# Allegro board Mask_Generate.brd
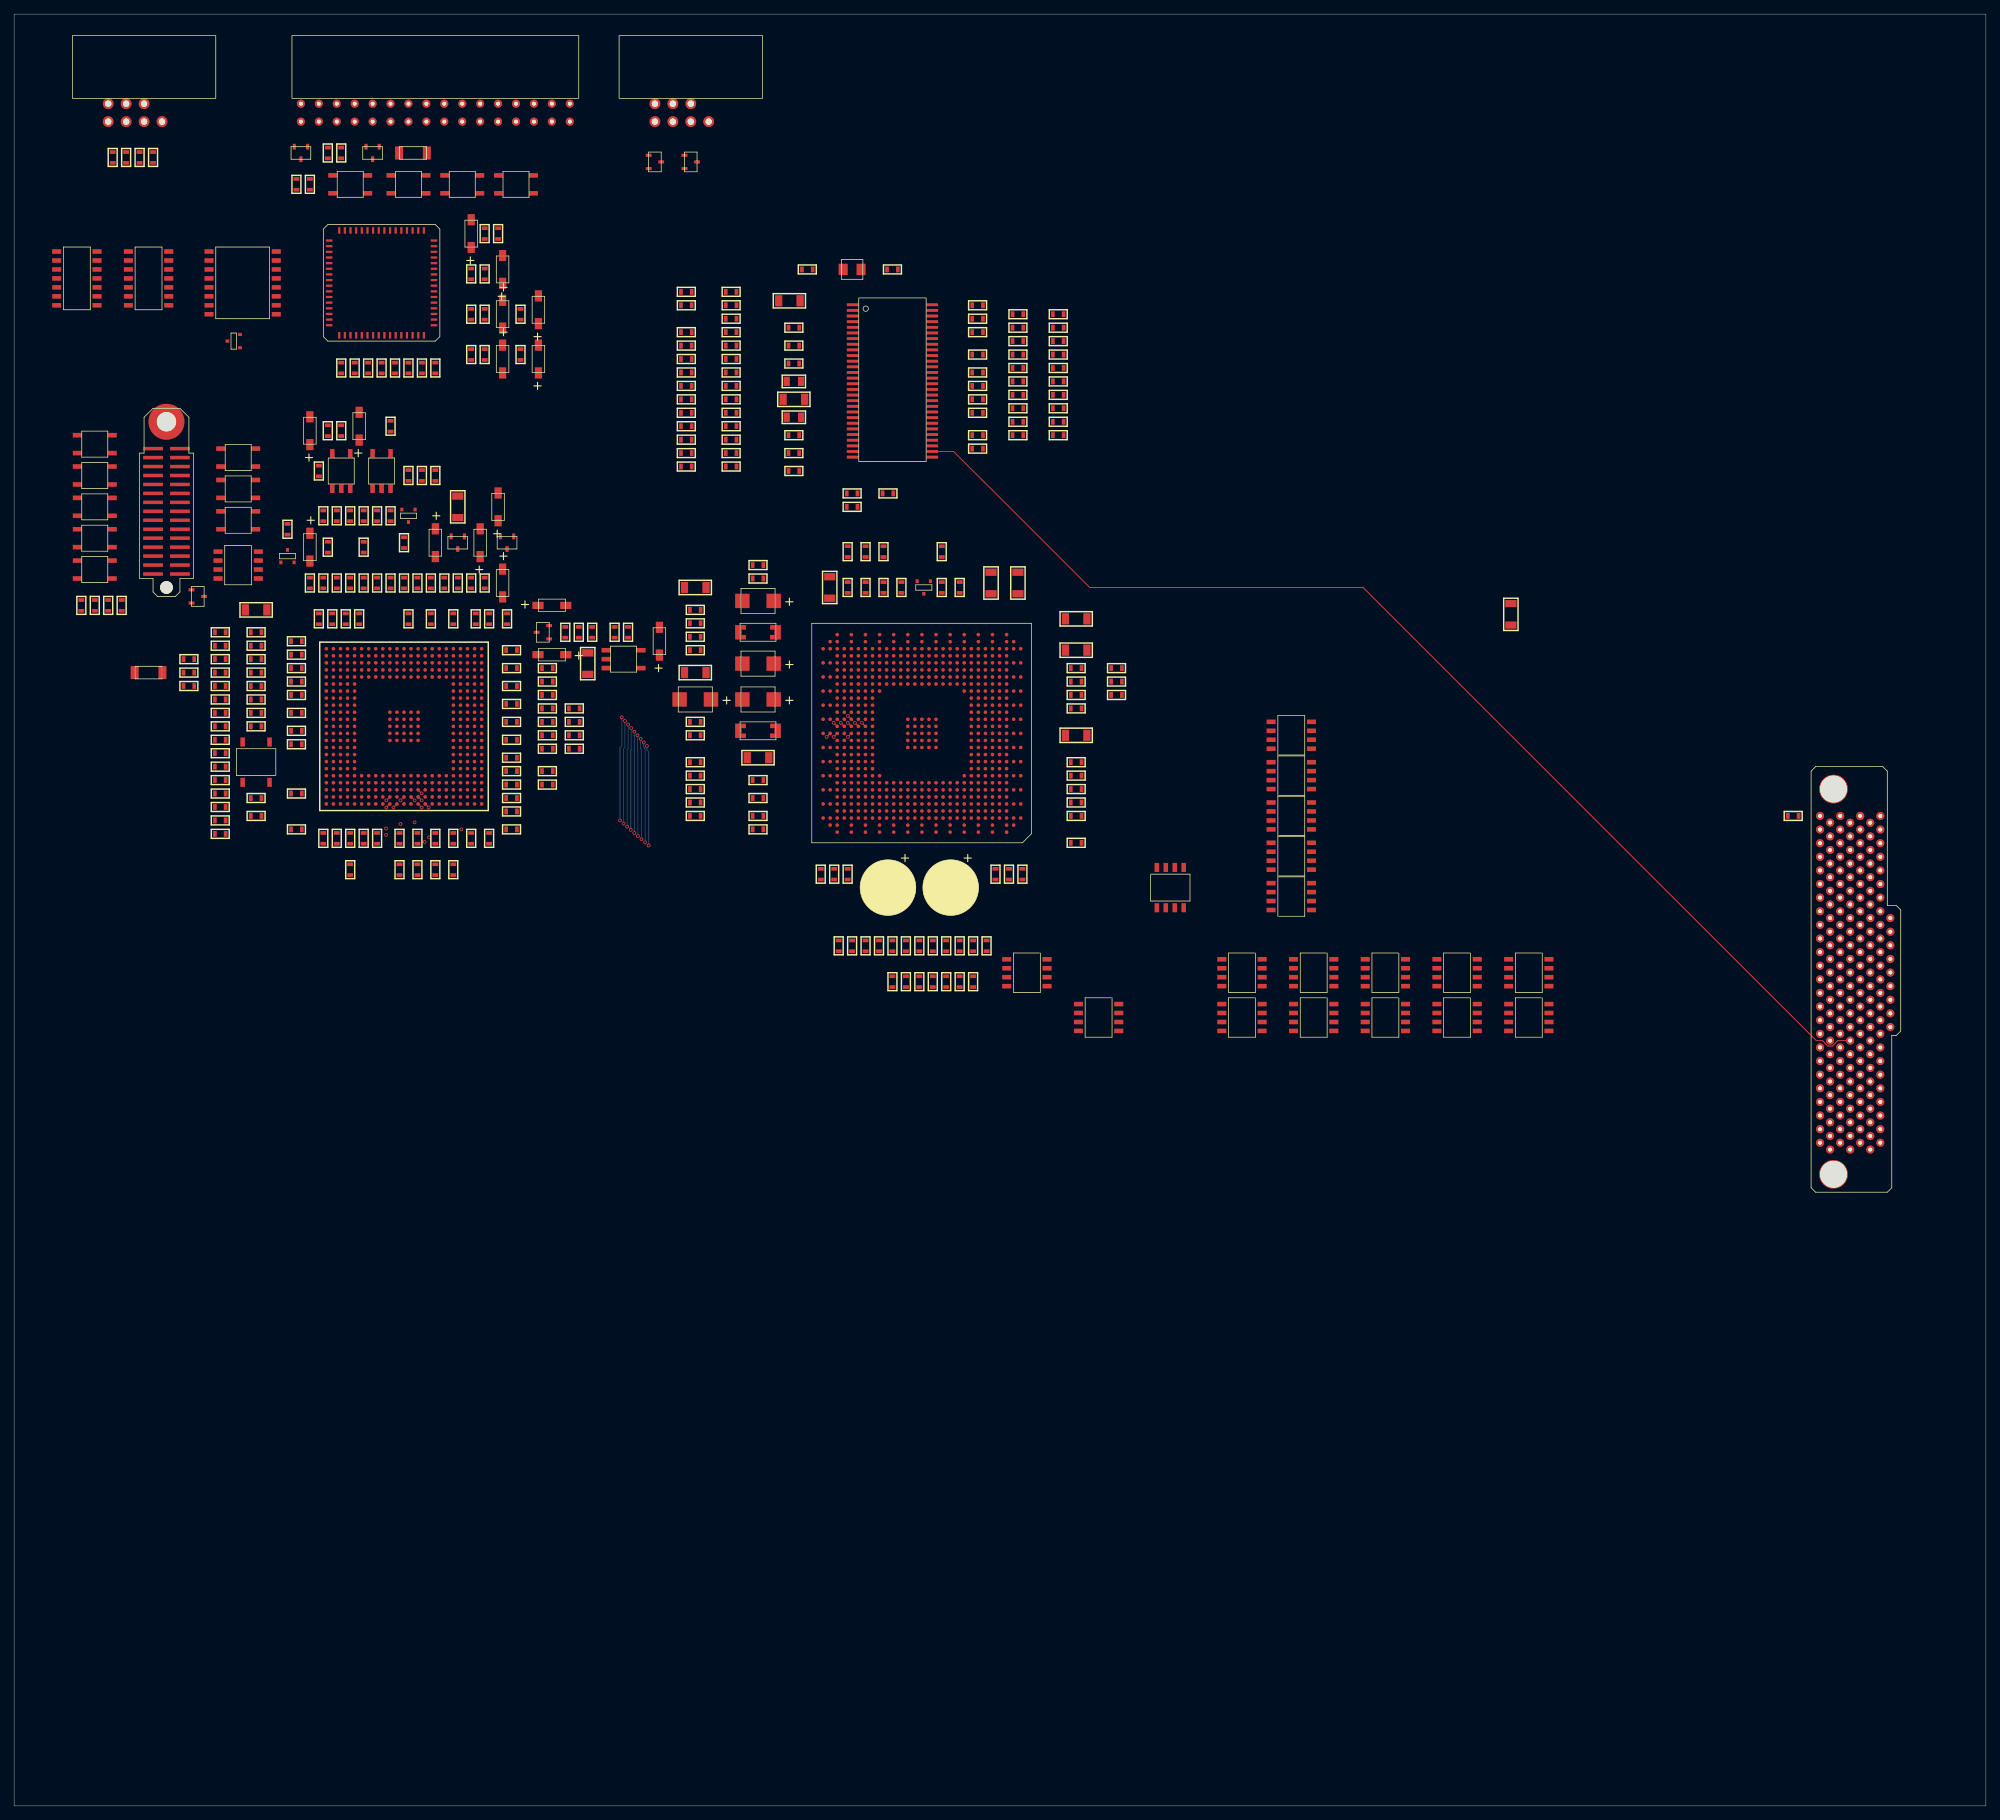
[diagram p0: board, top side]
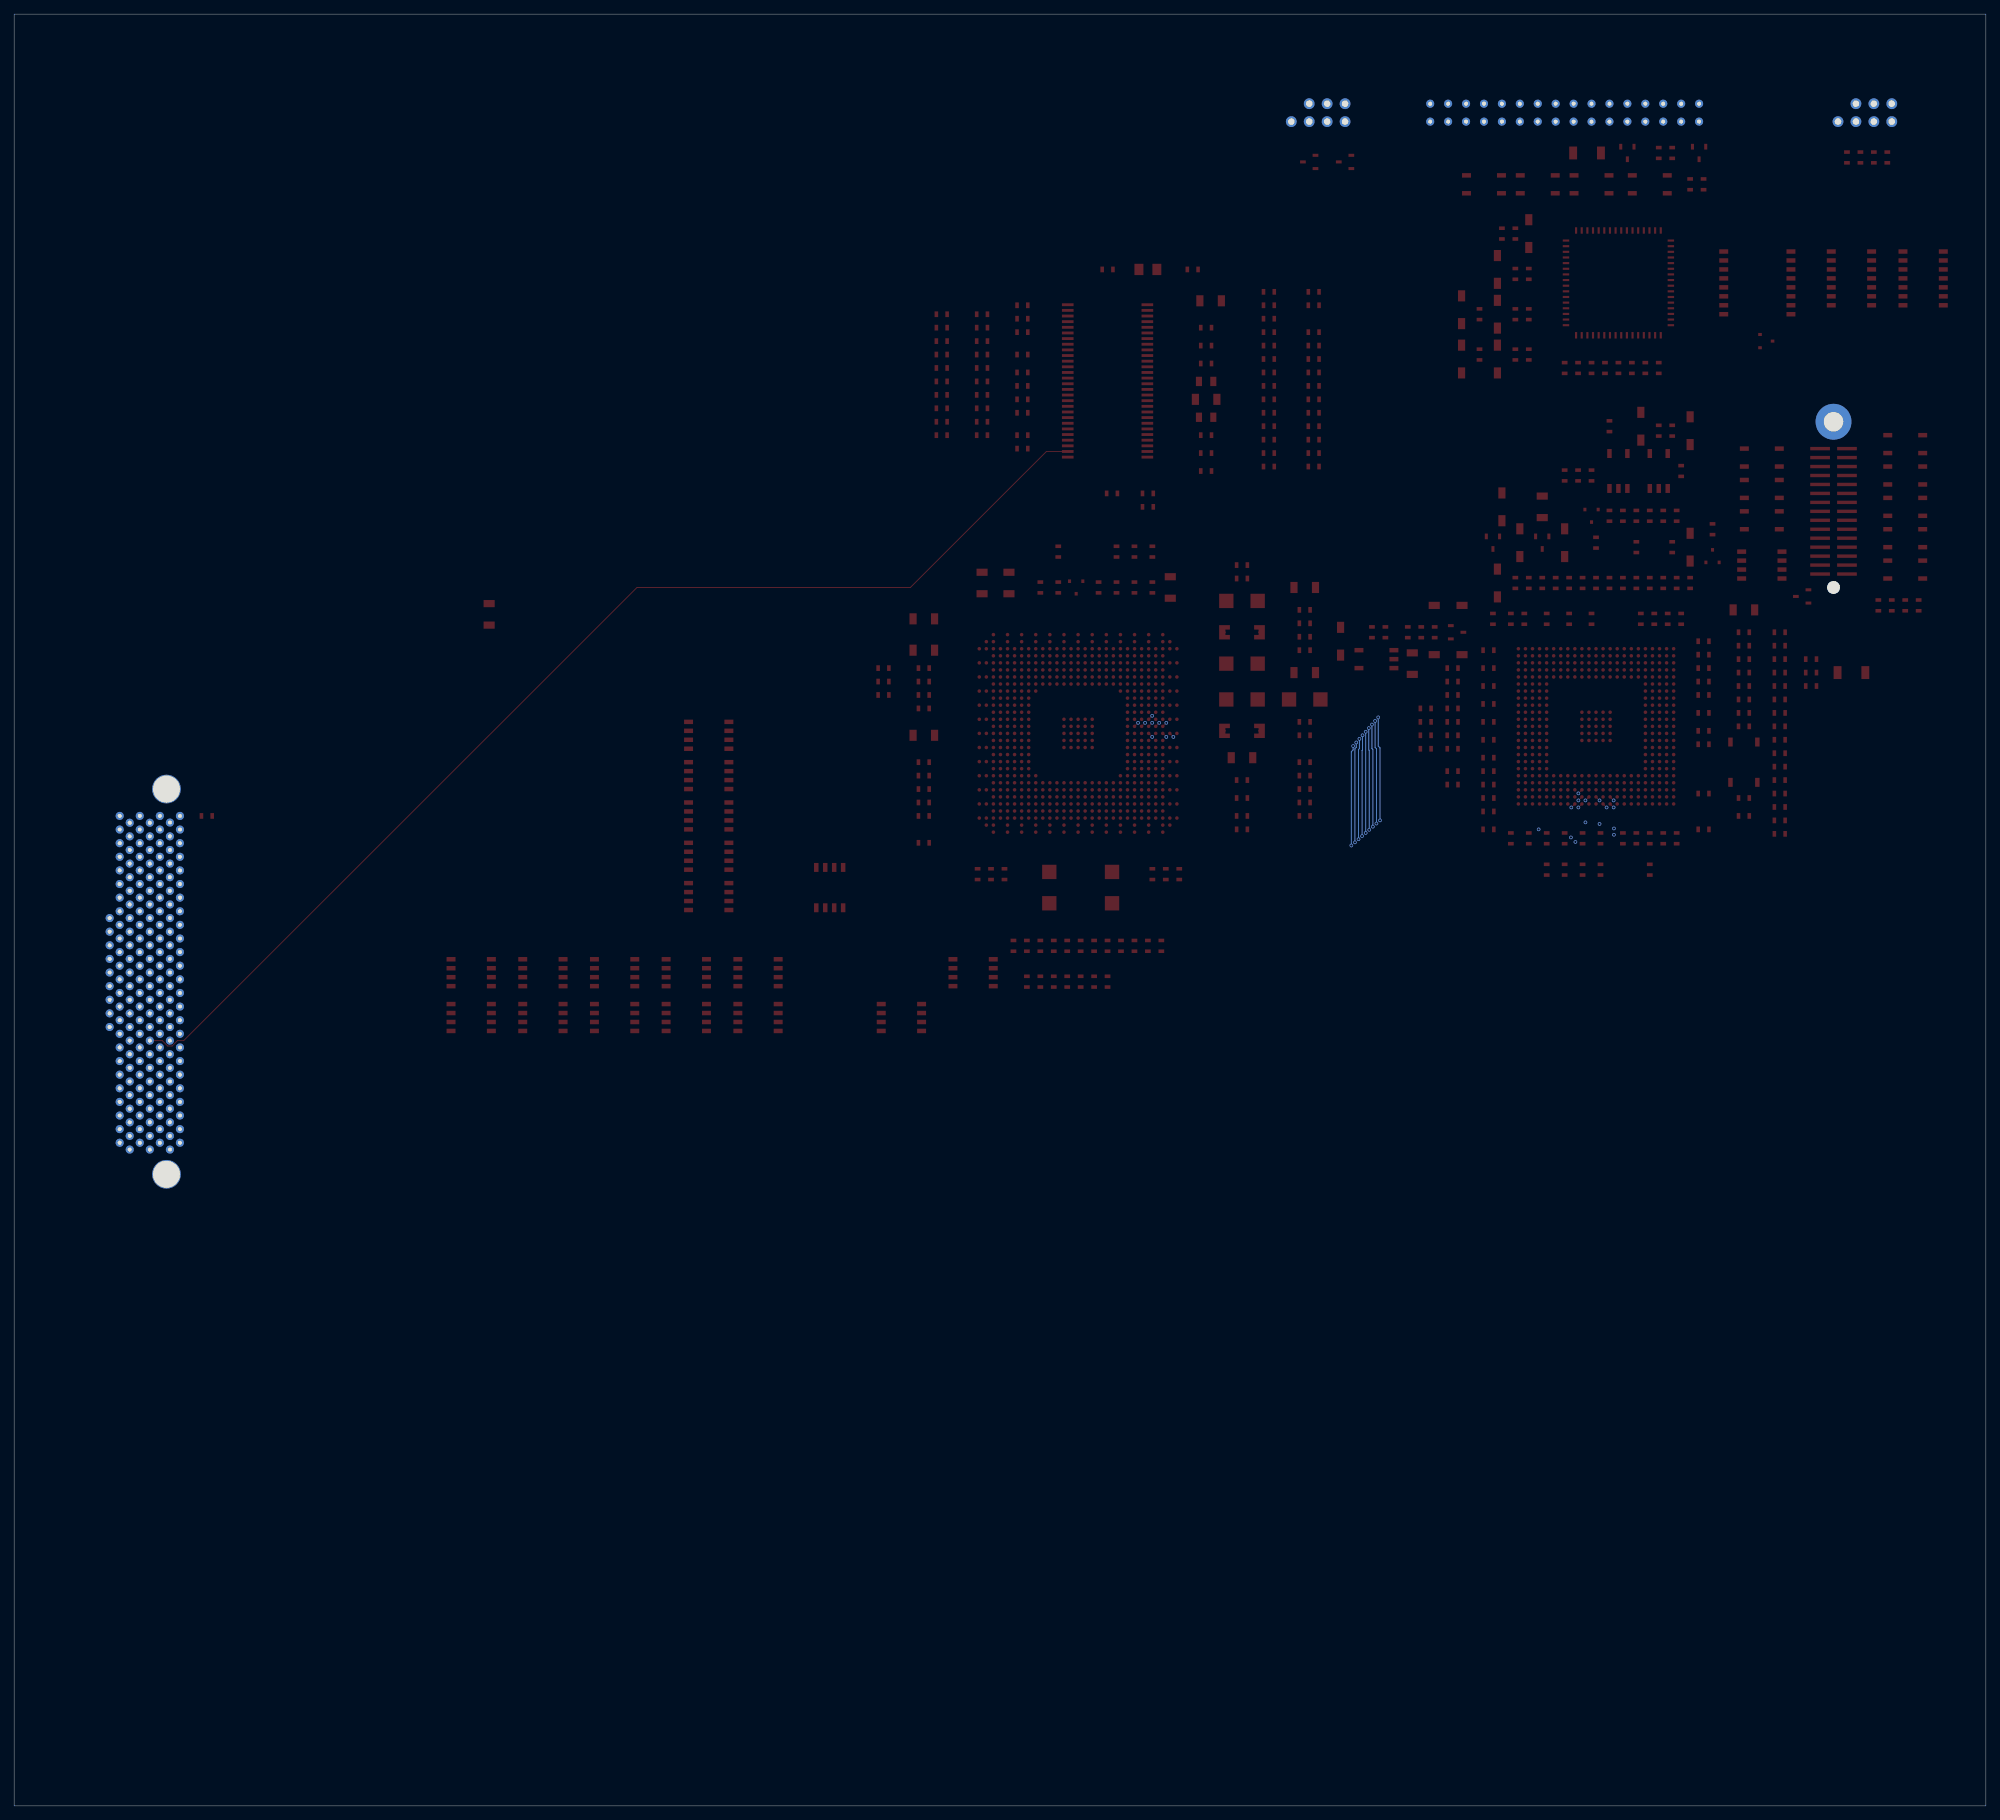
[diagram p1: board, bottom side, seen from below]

Outline 279.4 x 254 mm; copper layers: TOP, PLA2, INT3, INT4, PLA5, INT6, INT7, PLA8, INT9, INT10, PLA11, BOTTOM. Coordinates in mm from the lower left corner of the outline.
Outline path: 0,254 279.4,254 279.4,0 0,0 0,254

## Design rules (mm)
constraint set DEFAULT: min track width 0.127
net group ACTIVITY: nets ACT_1 ACTIVITY
net group AGP_REF: nets AGP_REF AGP_REFX
net group BSEL0: nets BSEL0 BSELX0
net group CK_14M: nets CK_14M CK_14MX
net group CK_27: nets CK_27 CK_PAL
net group CK_AGP66: nets CK_AGP66 CK_AGP66X
net group CK_CPLD: nets CK_CPLD CK_CPLDX
net group CK_CPU+: nets CK_CPU+ CK_CPUX+
net group CK_CPU-: nets CK_CPU- CK_CPUX-
net group CK_FWH: nets CK_FWH CK_FWHX
net group CK_ICH33: nets CK_ICH33 CK_ICH33X
net group CK_ICH48: nets CK_ICH48 CK_ICH48X
net group CK_ICH66: nets CK_ICH66 CK_ICH66X
net group CK_ITP+: nets CK_ITP+ CK_ITPX+
net group CK_ITP-: nets CK_ITP- CK_ITPX-
net group CK_LAN: nets CK_LAN CK_LANX
net group CK_LPC0: nets CK_LPC0 CK_LPC0X
net group CK_LPC1: nets CK_LPC1 CK_LPC1X
net group CK_MCH66: nets CK_MCH66 CK_MCH66X
net group CK_MCH+: nets CK_MCH+ CK_MCHX+
net group CK_MCH-: nets CK_MCH- CK_MCHX-
net group CK_MPCI: nets CK_MPCI CK_MPCIX
net group CK_RES0: nets CK_RES0 CK_RESX0
net group CK_RES1: nets CK_RES1 CK_RESX1
net group CK_RES2: nets CK_RES2 CK_RESX2
net group CK_SLOT1: nets CK_SLOT1 CK_SLOT1X
net group CK_SLOT2: nets CK_SLOT2 CK_SLOT2X
net group CK_SLOT3: nets CK_SLOT3 CK_SLOT3X
net group COMPFLT1: nets COMPFLT1 ITV_CVBS
net group DP1_CK_SCK+<0>: nets CK_SCK+<0> CK_SCK-<0>
net group DP1_CK_SCK+<5>: nets CK_SCK+<5> CK_SCK-<5>
net group DP_CK_SCK+<1>: nets CK_SCK+<1> CK_SCK-<1>
net group DP_CK_SCK+<2>: nets CK_SCK+<2> CK_SCK-<2>
net group DP_CK_SCK+<3>: nets CK_SCK+<3> CK_SCK-<3>
net group DP_CK_SCK+<4>: nets CK_SCK+<4> CK_SCK-<4>
net group DP_G_ADSTB0: nets G_ADSTB0+ G_ADSTB0-
net group DP_G_ADSTB1: nets G_ADSTB1+ G_ADSTB1-
net group DP_G_SBSTB: nets G_SBSTB+ G_SBSTB-
net group DP_H_DSTBN*<0>: nets H_DSTBN*<0> H_DSTBP*<0>
net group DP_H_DSTBN*<1>: nets H_DSTBN*<1> H_DSTBP*<1>
net group DP_H_DSTBN*<2>: nets H_DSTBN*<2> H_DSTBP*<2>
net group DP_H_DSTBN*<3>: nets H_DSTBN*<3> H_DSTBP*<3>
net group DP_H_HISTB: nets H_HISTB+ H_HISTB-
net group EXT_SWING: nets EXT_SWING V_AVCC1
net group G_AD<16>: nets G_AD<16> G_IDSEL
net group G_ST: nets G_ST<0> G_ST<2>
net group G_ST1X: nets G_ST1X G_ST<1>
net group H_ADSTB*: nets H_ADSTB*<0> H_ADSTB*<1>
net group M_D<0>: nets M_D<0> M_DX0
net group M_D<1>: nets M_D<1> M_DX1
net group M_D<2>: nets M_D<2> M_DX2
net group M_D<3>: nets M_D<3> M_DX3
net group M_D<4>: nets M_D<4> M_DX4
net group M_D<5>: nets M_D<5> M_DX5
net group M_D<6>: nets M_D<6> M_DX6
net group M_D<7>: nets M_D<7> M_DX7
net group M_D<8>: nets M_D<8> M_DX8
net group M_D<9>: nets M_D<9> M_DX9
net group M_D<10>: nets M_D<10> M_DX10
net group M_D<11>: nets M_D<11> M_DX11
net group M_D<12>: nets M_D<12> M_DX12
net group M_D<13>: nets M_D<13> M_DX13
net group M_D<14>: nets M_D<14> M_DX14
net group M_D<15>: nets M_D<15> M_DX15
net group M_D<16>: nets M_D<16> M_DX16
net group M_D<17>: nets M_D<17> M_DX17
net group M_D<18>: nets M_D<18> M_DX18
net group M_D<19>: nets M_D<19> M_DX19
net group M_D<20>: nets M_D<20> M_DX20
net group M_D<21>: nets M_D<21> M_DX21
net group M_D<22>: nets M_D<22> M_DX22
net group M_D<23>: nets M_D<23> M_DX23
net group M_D<24>: nets M_D<24> M_DX24
net group M_D<25>: nets M_D<25> M_DX25
net group M_D<26>: nets M_D<26> M_DX26
net group M_D<27>: nets M_D<27> M_DX27
net group M_D<28>: nets M_D<28> M_DX28
net group M_D<29>: nets M_D<29> M_DX29
net group M_D<30>: nets M_D<30> M_DX30
net group M_D<31>: nets M_D<31> M_DX31
net group M_D<32>: nets M_D<32> M_DX32
net group M_D<33>: nets M_D<33> M_DX33
net group M_D<34>: nets M_D<34> M_DX34
net group M_D<35>: nets M_D<35> M_DX35
net group M_D<36>: nets M_D<36> M_DX36
net group M_D<37>: nets M_D<37> M_DX37
net group M_D<38>: nets M_D<38> M_DX38
net group M_D<39>: nets M_D<39> M_DX39
net group M_D<40>: nets M_D<40> M_DX40
net group M_D<41>: nets M_D<41> M_DX41
net group M_D<42>: nets M_D<42> M_DX42
net group M_D<43>: nets M_D<43> M_DX43
net group M_D<44>: nets M_D<44> M_DX44
net group M_D<45>: nets M_D<45> M_DX45
net group M_D<46>: nets M_D<46> M_DX46
net group M_D<47>: nets M_D<47> M_DX47
net group M_D<48>: nets M_D<48> M_DX48
net group M_D<49>: nets M_D<49> M_DX49
net group M_D<50>: nets M_D<50> M_DX50
net group M_D<51>: nets M_D<51> M_DX51
net group M_D<52>: nets M_D<52> M_DX52
net group M_D<53>: nets M_D<53> M_DX53
net group M_D<54>: nets M_D<54> M_DX54
net group M_D<55>: nets M_D<55> M_DX55
net group M_D<56>: nets M_D<56> M_DX56
net group M_D<57>: nets M_D<57> M_DX57
net group M_D<58>: nets M_D<58> M_DX58
net group M_D<59>: nets M_D<59> M_DX59
net group M_D<60>: nets M_D<60> M_DX60
net group M_D<61>: nets M_D<61> M_DX61
net group M_D<62>: nets M_D<62> M_DX62
net group M_D<63>: nets M_D<63> M_DX63
net group M_SBS0: nets M_SBS0 M_SBSX0
net group M_SBS1: nets M_SBS1 M_SBSX1
net group M_SCAS*: nets M_SCAS* M_SCASX*
net group M_SCB<0>: nets M_SCB<0> M_SCBX0
net group M_SCB<1>: nets M_SCB<1> M_SCBX1
net group M_SCB<2>: nets M_SCB<2> M_SCBX2
net group M_SCB<3>: nets M_SCB<3> M_SCBX3
net group M_SCB<4>: nets M_SCB<4> M_SCBX4
net group M_SCB<5>: nets M_SCB<5> M_SCBX5
net group M_SCB<6>: nets M_SCB<6> M_SCBX6
net group M_SCB<7>: nets M_SCB<7> M_SCBX7
net group M_SDQS<0>: nets M_SDQS<0> M_SDQSX0
net group M_SDQS<1>: nets M_SDQS<1> M_SDQSX1
net group M_SDQS<2>: nets M_SDQS<2> M_SDQSX2
net group M_SDQS<3>: nets M_SDQS<3> M_SDQSX3
net group M_SDQS<4>: nets M_SDQS<4> M_SDQSX4
net group M_SDQS<5>: nets M_SDQS<5> M_SDQSX5
net group M_SDQS<6>: nets M_SDQS<6> M_SDQSX6
net group M_SDQS<7>: nets M_SDQS<7> M_SDQSX7
net group M_SDQS<8>: nets M_SDQS<8> M_SDQSX8
net group M_SMA<0>: nets M_SMA<0> M_SMAX0
net group M_SMA<1>: nets M_SMA<1> M_SMAX1
net group M_SMA<2>: nets M_SMA<2> M_SMAX2
net group M_SMA<3>: nets M_SMA<3> M_SMAX3
net group M_SMA<4>: nets M_SMA<4> M_SMAX4
net group M_SMA<5>: nets M_SMA<5> M_SMAX5
net group M_SMA<6>: nets M_SMA<6> M_SMAX6
net group M_SMA<7>: nets M_SMA<7> M_SMAX7
net group M_SMA<8>: nets M_SMA<8> M_SMAX8
net group M_SMA<9>: nets M_SMA<9> M_SMAX9
net group M_SMA<10>: nets M_SMA<10> M_SMAX10
net group M_SMA<11>: nets M_SMA<11> M_SMAX11
net group M_SMA<12>: nets M_SMA<12> M_SMAX12
net group M_SRAS*: nets M_SRAS* M_SRASX*
net group M_SWE*: nets M_SWE* M_SWEX*
net group MSEN: nets MSEN MSENX
net group MVREF: nets MVREF V_VDD2
net group TMDS0+: nets TMDS0+ TMDS0C+
net group TMDS0-: nets TMDS0- TMDS0C-
net group TMDS1+: nets TMDS1+ TMDS1C+
net group TMDS1-: nets TMDS1- TMDS1C-
net group TMDS2+: nets TMDS2+ TMDS2C+
net group TMDS2-: nets TMDS2- TMDS2C-
net group TMDSCLK+: nets TMDSCLK+ TMDSCLKC+
net group TMDSCLK-: nets TMDSCLK- TMDSCLKC-
net group TX0+: nets TX0+ TX0C+
net group TX0-: nets TX0- TX0C-
net group TX1+: nets TX1+ TX1C+
net group TX1-: nets TX1- TX1C-
net group TX2+: nets TX2+ TX2C+
net group TX2-: nets TX2- TX2C-
net group TX5+: nets TX5+ TX5C+
net group TX5-: nets TX5- TX5C-
net group TX6+: nets TX6+ TX6C+
net group TX6-: nets TX6- TX6C-
net group TXCLK1+: nets TXCLK1+ TXCLK1C+
net group TXCLK1-: nets TXCLK1- TXCLK1C-
net group TXCLK2+: nets TXCLK2+ TXCLK2C+
net group TXCLK2-: nets TXCLK2- TXCLK2C-
net group ACT_2: nets ACT_2 ADJ_VDD1 EN_LVD V_2V0_2V5
net group ADJ_LVD: nets ADJ_LVD ADJ_VDD2 V_2V5_LVD V_2V5_LVD1 V_2V5_LVD2 V_2V5_VDD
net group G_AD: nets G_AD<0> G_AD<1> G_AD<2> G_AD<3> G_AD<4> G_AD<5> G_AD<6> G_AD<7> G_AD<8> G_AD<9> G_AD<10> G_AD<11> G_AD<12> G_AD<13> G_AD<14> G_AD<15> G_AD<17> G_AD<18> G_AD<19> G_AD<20> G_AD<21> G_AD<22> G_AD<23> G_AD<24> G_AD<25> G_AD<26> G_AD<27> G_AD<28> G_AD<29> G_AD<30> G_AD<31>
net group G_C/BE*: nets G_C/BE*<0> G_C/BE*<1> G_C/BE*<2> G_C/BE*<3>
net group G_SBA: nets G_SBA<0> G_SBA<1> G_SBA<2> G_SBA<3> G_SBA<4> G_SBA<5> G_SBA<6> G_SBA<7>
net group H_A*: nets H_A*<3> H_A*<4> H_A*<5> H_A*<6> H_A*<7> H_A*<8> H_A*<9> H_A*<10> H_A*<11> H_A*<12> H_A*<13> H_A*<14> H_A*<15> H_A*<16> H_A*<17> H_A*<18> H_A*<19> H_A*<20> H_A*<21> H_A*<22> H_A*<23> H_A*<24> H_A*<25> H_A*<26> H_A*<27> H_A*<28> H_A*<29> H_A*<30> H_A*<31>
net group H_CPURST*: nets H_CPURST*
net group H_D: nets H_D<0> H_D<1> H_D<2> H_D<3> H_D<4> H_D<5> H_D<6> H_D<7> H_D<8> H_D<9> H_D<10> H_D<11> H_D<12> H_D<13> H_D<14> H_D<15> H_D<16> H_D<17> H_D<18> H_D<19> H_D<20> H_D<21> H_D<22> H_D<23> H_D<24> H_D<25> H_D<26> H_D<27> H_D<28> H_D<29> H_D<30> H_D<31> H_D<32> H_D<33> H_D<34> H_D<35> H_D<36> H_D<37> H_D<38> H_D<39> H_D<40> H_D<41> H_D<42> H_D<43> H_D<44> H_D<45> H_D<46> H_D<47> H_D<48> H_D<49> H_D<50> H_D<51> H_D<52> H_D<53> H_D<54> H_D<55> H_D<56> H_D<57> H_D<58> H_D<59> H_D<60> H_D<61> H_D<62> H_D<63>
net group H_DBI*: nets H_DBI*<0> H_DBI*<1> H_DBI*<2> H_DBI*<3>
net group H_HI: nets H_HI<0> H_HI<1> H_HI<2> H_HI<3> H_HI<4> H_HI<5> H_HI<6> H_HI<7> H_HI<8> H_HI<9> H_HI<10>
net group H_REQ*: nets H_REQ*<0> H_REQ*<1> H_REQ*<2> H_REQ*<3> H_REQ*<4>
net group H_RS*: nets H_RS*<0> H_RS*<1> H_RS*<2>
net group M_SCKE: nets M_SCKE<0> M_SCKE<1> M_SCKE<2> M_SCKE<3>
net group M_SCS*: nets M_SCS*<0> M_SCS*<1> M_SCS*<2> M_SCS*<3>
net group TX3+: nets TX3+ TX3_4+ TX3_4C+ TX4+
net group TX3-: nets TX3- TX3_4- TX3_4C- TX4-

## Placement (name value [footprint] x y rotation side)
C1  0.01PF  [C1206]  212.09 168.91 270 top
C61  0.1PF  [C0603]  96.52 153.67 180 top
C62  0.01PF  [C0603]  156.21 161.29 0 top
C63  0.01PF  [C0603]  96.52 151.76 180 top
C64  0.1PF  [C1206]  115.57 172.72 90 top
C65  0.1PF  [C1206]  138.43 173.35 90 top
C66  0.1PF  [C1206]  142.24 173.35 90 top
C67  0.1PF  [C0603]  150.49 147.95 0 top
C68  0.1PF  [C1206]  150.49 151.76 0 top
C69  10UF  [C1206]  150.49 163.83 0 top
C70  33UF  [TAJC]  105.41 156.84 180 top
C71  33UF  [TAJC]  105.41 161.92 180 top
C72  10UF  [C1206]  150.49 168.27 0 top
C73  0.1PF  [C0603]  96.52 147.95 180 top
C74  0.1PF  [C0603]  150.49 155.57 0 top
C75  100UF  [ELK01G]  132.72 130.17 270 top
C76  100UF  [TAJC]  96.52 156.84 180 top
C77  100UF  [ELK01G]  123.83 130.17 270 top
C78  100UF  [TAJC]  105.41 170.81 180 top
C79  0.1PF  [C0603]  118.11 132.08 270 top
C80  10UF  [C1206]  96.52 172.72 180 top
C81  10UF  [C1206]  105.41 148.59 180 top
C82  0.1PF  [C0603]  116.2 132.08 270 top
C83  10UF  [C1206]  96.52 160.66 180 top
C84  0.1PF  [C0603]  114.3 132.08 270 top
C85  0.1PF  [C0603]  142.88 132.08 270 top
C86  0.1PF  [C0603]  96.52 169.54 180 top
C87  0.1PF  [C0603]  105.41 140.34 180 top
C88  0.1PF  [C0603]  140.97 132.08 270 top
C89  0.1PF  [C0603]  105.41 175.89 180 top
C90  0.1PF  [C0603]  105.41 142.88 180 top
C91  0.1PF  [C0603]  139.06 132.08 270 top
C92  0.1PF  [C0603]  105.41 173.99 180 top
C93  0.1PF  [C0603]  105.41 145.41 180 top
C94  0.1PF  [C0603]  96.52 167.64 180 top
C95  0.1PF  [C0603]  96.52 165.73 180 top
C96  0.1PF  [C0603]  96.52 163.83 180 top
C97  10UF  [C1206]  109.86 213.36 180 top
C98  10UF  [C1206]  110.49 199.39 0 top
C99  0.1PF  [C0603]  110.49 194.31 180 top
C100  0.1PF  [C0603]  136.53 194.31 0 top
C101  0.1PF  [C0603]  110.49 191.77 180 top
C102  0.1PF  [C0603]  110.49 189.23 180 top
C103  0.01PF  [C0603]  110.49 209.55 180 top
C104  0.1PF  [C0603]  136.53 208.91 0 top
C105  0.01PF  [C0603]  110.49 204.47 180 top
C106  0.1PF  [C0603]  136.53 205.74 0 top
C107  0.01PF  [C0603]  110.49 207.01 180 top
C108  10PF  [C0603]  112.39 217.8 180 top
C109  10PF  [C0603]  124.46 217.8 0 top
C110  10PF  [C0603]  95.25 189.86 180 top
C111  10F  [C0603]  95.25 191.77 0 top
C112  10PF  [C0603]  95.25 193.67 0 top
C113  10PF  [C0603]  147.95 194.31 0 top
C114  10PF  [C0603]  147.95 196.21 0 top
C115  10PF  [C0603]  95.25 195.58 180 top
C116  10PF  [C0603]  147.95 198.12 180 top
C117  10PF  [C0603]  95.25 214.63 180 top
C118  10F  [C0603]  95.25 212.72 180 top
C119  10PF  [C0603]  95.25 208.91 0 top
C120  10PF  [C0603]  95.25 207.01 0 top
C121  10PF  [C0603]  95.25 205.1 0 top
C122  10PF  [C0603]  95.25 203.2 0 top
C123  10PF  [C0603]  95.25 201.29 0 top
C124  10PF  [C0603]  95.25 199.39 0 top
C125  10PF  [C0603]  95.25 197.48 180 top
C126  10PF  [C0603]  147.95 211.45 0 top
C127  0.1PF  [C0603]  252.09 140.34 180 top
C207  0.1PF  [C0603]  34.29 140.34 180 top
C208  0.1PF  [C0603]  64.77 205.74 270 top
C209  0.1PF  [C0603]  68.58 222.88 90 top
C210  0.1PF  [C0603]  64.77 211.45 270 top
C211  0.1PF  [C0603]  48.26 203.83 270 top
C212  0.1PF  [C0603]  66.67 205.74 270 top
C213  0.1PF  [C0603]  66.67 222.88 90 top
C214  0.1PF  [C0603]  66.67 211.45 270 top
C215  4UF  [TAJA]  69.22 205.1 270 top
C216  4UF  [TAJA]  64.77 222.88 90 top
C217  22UF  [TAJA]  69.22 211.45 270 top
C218  100PF  [C0603]  29.21 166.37 180 top
C219  22UF  [TAJA]  74.3 205.1 90 top
C220  22UF  [TAJA]  69.22 217.8 90 top
C221  22UF  [TAJA]  74.3 212.09 90 top
C222  47PF  [C0603]  29.21 160.66 180 top
C223  220PF  [C0603]  24.77 162.56 180 top
C224  0.1PF  [C0603]  44.45 234.31 270 top
C225  0.1PF  [C0603]  46.36 234.31 90 top
C226  22UF  [TAJA]  41.91 194.94 90 top
C227  22UF  [TAJA]  48.89 195.58 90 top
C228  22UF  [TAJA]  91.44 165.1 90 top
C229  0.1PF  [C0603]  46.36 194.94 90 top
C230  100PF  [C0603]  47.62 182.88 270 top
C231  100PF  [C0603]  51.44 182.88 270 top
C232  100PF  [C0603]  81.92 166.37 90 top
C233  4UF  [TAJA]  41.91 178.44 270 top
C234  22UF  [TAJA]  59.69 179.07 270 top
C235  0.1PF  [C0603]  55.25 179.07 270 top
C236  0.1PF  [C0603]  78.11 166.37 90 top
C237  22UF  [TAJA]  68.58 184.15 90 top
C238  22UF  [TAJA]  76.2 163.19 180 top
C239  4UF  [TAJA]  66.04 179.07 90 top
C240  4UF  [TAJA]  69.22 173.35 270 top
C241  4UF  [TAJA]  76.2 170.18 0 top
C242  0.1PF  [C0603]  75.56 144.78 0 top
C243  0.1PF  [C0603]  47.62 137.16 270 top
C244  0.1PF  [C0603]  40 163.19 180 top
C245  0.1PF  [C0603]  43.81 137.16 270 top
C246  0.1PF  [C0603]  70.48 142.88 0 top
C247  0.1PF  [C0603]  45.08 168.27 90 top
C248  0.1PF  [C0603]  70.48 138.43 0 top
C249  0.1PF  [C0603]  40 143.51 180 top
C250  0.1PF  [C0603]  67.31 137.16 270 top
C251  0.1PF  [C0603]  70.48 153.67 0 top
C252  0.1PF  [C0603]  46.99 168.27 90 top
C253  0.1PF  [C0603]  70.48 148.59 0 top
C254  0.1PF  [C0603]  62.23 168.27 90 top
C255  0.1PF  [C0603]  70.48 151.13 0 top
C256  0.1PF  [C0603]  57.15 137.16 270 top
C257  0.1PF  [C0603]  34.29 160.66 180 top
C258  0.1PF  [C0603]  34.29 154.94 180 top
C259  0.1PF  [C0603]  34.29 164.46 0 top
C260  0.1PF  [C0603]  29.21 147.32 180 top
C261  0.1PF  [C0603]  29.21 137.79 180 top
C262  0.1PF  [C0603]  47.62 173.35 90 top
C263  0.1PF  [C0603]  59.05 173.35 90 top
C264  0.1PF  [C0603]  57.15 173.35 90 top
C265  0.1PF  [C0603]  45.72 173.35 90 top
C266  0.1PF  [C0603]  40 157.48 180 top
C267  0.1PF  [C0603]  69.85 168.27 90 top
C268  0.1PF  [C0603]  70.48 140.97 0 top
C269  0.1PF  [C0603]  70.48 156.21 0 top
C270  0.1PF  [C0603]  62.23 137.16 270 top
C271  0.01PF  [C0603]  34.29 166.37 0 top
C272  0.1PF  [C0603]  29.21 139.7 180 top
C273  0.01PF  [C0603]  51.44 173.35 90 top
C274  0.01PF  [C0603]  62.86 173.35 90 top
C275  0.01PF  [C0603]  53.34 173.35 90 top
C276  0.01PF  [C0603]  41.91 173.35 90 top
C277  0.1PF  [C0603]  40 159.38 180 top
C278  0.1PF  [C0603]  67.31 168.27 90 top
C279  0.1PF  [C0603]  40 154.94 180 top
C280  0.1PF  [C0603]  70.48 161.29 0 top
C281  0.1PF  [C0603]  70.48 163.83 0 top
C282  0.1PF  [C0603]  29.21 141.6 180 top
C283  0.1PF  [C0603]  40 161.29 180 top
C284  0.1PF  [C0603]  65.41 168.27 90 top
C285  0.1PF  [C0603]  40 138.43 180 top
C286  0.1PF  [C0603]  64.77 137.16 270 top
C287  0.1PF  [C0603]  54.61 137.16 270 top
C288  0.1PF  [C0603]  29.21 143.51 180 top
C289  0.1PF  [C0603]  40 165.1 180 top
C290  0.1PF  [C0603]  55.88 168.27 90 top
C291  0.1PF  [C0603]  70.48 144.78 0 top
C292  0.1PF  [C0603]  70.48 158.75 0 top
C293  0.1PF  [C0603]  59.69 137.16 270 top
CF1  NFM60R30T222  [FM03ASMD]  90.81 233.04 0 top
CF2  NFM60R30T222  [FM03ASMD]  95.89 233.04 0 top
CF3  NFM60R30T222  [FM03ASMD]  26.04 171.45 0 top
CF4  NFM60R30T222  [FM03ASMD]  50.8 234.31 270 top
CF5  NFM60R30T222  [FM03ASMD]  40.64 234.31 270 top
CF6  NFM60R30T222  [FM03ASMD]  62.86 179.07 270 top
CF7  NFM60R30T222  [FM03ASMD]  69.85 179.07 270 top
CF8  NFM60R30T222  [FM03ASMD]  74.93 166.37 180 top
CN2  DIMM  [DIMM184A]  255.91 140.34 0 top
CN4  SM07/FA  [CON07ASMD]  90.81 238.76 0 top
CN5  SW30/VJ  [CON30FSMD]  21.59 182.88 180 top
CN6  SW04/RB  [CON07DF]  13.33 238.76 0 top
D1  BAT54  [SOT23B]  31.11 207.64 180 top
F1  SMD075-2  [C1812]  56.52 234.31 0 top
FB1  BLM21B601S  [C0805]  110.49 196.85 0 top
FB2  BLM21B601S  [C0805]  110.49 201.93 0 top
FB3  BLM11A601SPT  [C0603]  71.75 205.74 270 top
FB4  BLM11A601SPT  [C0603]  66.67 217.17 270 top
FB5  BLM11A601SPT  [C0603]  71.75 211.45 270 top
FB6  BLM11A601SPT  [C0603]  29.21 162.56 180 top
FB7  BLM11A601SPT  [C0603]  24.77 160.66 180 top
FB8  BLM11A601SPT  [C0603]  17.78 233.68 270 top
FB9  BLM11A601SPT  [C0603]  15.88 233.68 270 top
FB10  BLM11A601SPT  [C0603]  34.29 158.75 0 top
FB11  BLM11A601SPT  [C0603]  34.29 156.84 0 top
FB12  BLM11A601SPT  [C0603]  34.29 162.56 0 top
FB13  BLM11A601SPT  [C0603]  34.29 153.03 0 top
FB14  BLM11A601SPT  [C0603]  29.21 145.41 0 top
FB15  BLM11A601SPT  [C0603]  49.53 173.35 270 top
FB16  BLM11A601SPT  [C0603]  60.96 173.35 270 top
FB17  BLM11A601SPT  [C0603]  55.25 173.35 270 top
FB18  BLM11A601SPT  [C0603]  43.81 173.35 270 top
JP1  SM02/RA  [WWS02]  19.05 160.66 180 top
L3  4u  [IND02GSMD]  105.41 152.4 0 top
L4  4uH  [IND02GSMD]  105.41 166.37 0 top
L5  PLW3216S102  [IND04DSMD]  11.43 188.59 180 top
L6  PLW3216S102  [IND04DSMD]  11.43 184.15 0 top
L7  PLW3216S102  [IND04DSMD]  11.43 179.7 180 top
L8  PLW3216S102  [IND04DSMD]  11.43 193.04 180 top
L9  PLW3216S102  [IND04DSMD]  31.75 191.13 180 top
L10  PLW3216S102  [IND04DSMD]  31.75 186.69 180 top
L11  PLW3216S102  [IND04DSMD]  31.75 182.24 180 top
L12  PLW3216S102  [IND04DSMD]  11.43 175.26 180 top
L13  PLW3216S102  [IND04DSMD]  47.62 229.87 180 top
L14  PLW3216S102  [IND04DSMD]  55.88 229.87 180 top
L15  PLW3216S102  [IND04DSMD]  63.5 229.87 180 top
L16  PLW3216S102  [IND04DSMD]  71.12 229.87 180 top
Q1  BC847B  [SOT23B]  128.91 172.72 270 top
Q2  SI4425DY  [SO08]  31.75 175.89 180 top
Q3  2N7002/B  [SOT23B]  38.73 177.16 90 top
Q4  2N7002/B  [SOT23B]  55.88 182.88 270 top
R56  1K  [C0603]  126.37 116.84 270 top
R57  1.5K  [C0603]  131.44 172.72 270 top
R58  1K  [C0603]  125.73 172.72 270 top
R59  1K  [C0603]  123.19 172.72 90 top
R60  6K  [C0603]  120.65 177.8 90 top
R61  2K  [C0603]  120.65 172.72 90 top
R62  10  [C0603]  123.19 177.8 270 top
R63  40  [C0603]  118.11 177.8 270 top
R64  2K  [C0603]  118.11 172.72 90 top
R65  10  [C0603]  116.84 121.92 270 top
R66  10  [C0603]  133.98 121.92 270 top
R67  10  [C0603]  135.89 121.92 270 top
R68  10  [C0603]  96.52 140.34 180 top
R69  10  [C0603]  96.52 146.05 180 top
R70  10  [C0603]  118.75 121.92 270 top
R71  10  [C0603]  122.56 121.92 270 top
R72  10  [C0603]  124.46 121.92 270 top
R73  10  [C0603]  124.46 116.84 270 top
R74  10  [C0603]  133.98 172.72 90 top
R75  10  [C0603]  130.17 116.84 270 top
R76  10  [C0603]  128.27 116.84 270 top
R77  10  [C0603]  133.98 116.84 270 top
R78  33  [C0603]  128.27 121.92 270 top
R79  33  [C0603]  150.49 140.34 0 top
R80  33  [C0603]  137.79 121.92 270 top
R81  33  [C0603]  135.89 116.84 270 top
R82  33  [C0603]  132.08 116.84 270 top
R83  33  [C0603]  126.37 121.92 270 top
R84  33  [C0603]  120.65 121.92 270 top
R85  33  [C0603]  96.52 142.24 180 top
R86  33  [C0603]  96.52 144.14 180 top
R87  10  [C0603]  130.17 121.92 270 top
R88  10  [C0603]  132.08 121.92 270 top
R89  10  [C0603]  150.49 142.24 180 top
R90  10  [C0603]  150.49 144.14 0 top
R91  10  [C0603]  150.49 146.05 0 top
R92  300  [C0603]  156.21 159.38 0 top
R93  150  [C0603]  156.21 157.48 180 top
R94  24  [C0603]  131.44 177.8 270 top
R95  24  [C0603]  150.49 161.29 180 top
R96  30  [C0603]  150.49 136.53 0 top
R97  40  [C0603]  105.41 138.43 180 top
R98  49  [C0603]  150.49 157.48 180 top
R99  100  [C0603]  150.49 159.38 0 top
R100  1K  [C0603]  136.53 192.41 0 top
R101  1K  [C0603]  136.53 210.82 180 top
R102  1K  [C0603]  123.83 186.05 0 top
R103  1K  [C0603]  118.75 184.15 0 top
R104  1K  [C0603]  118.75 186.05 0 top
R105  10K  [C0603]  136.53 201.29 0 top
R106  1K  [C0603]  136.53 199.39 0 top
R107  1K  [C0603]  136.53 197.48 0 top
R108  1K  [C0603]  136.53 212.72 180 top
R109  475  [C0603]  136.53 203.2 0 top
R110  27  [C0603]  142.24 209.55 180 top
R111  27  [C0603]  142.24 207.64 180 top
R112  27  [C0603]  142.24 205.74 180 top
R113  27  [C0603]  142.24 203.83 180 top
R114  27  [C0603]  142.24 201.93 180 top
R115  27  [C0603]  142.24 200.02 180 top
R116  33  [C0603]  142.24 194.31 180 top
R117  33  [C0603]  142.24 196.21 180 top
R118  33  [C0603]  101.6 195.58 0 top
R119  33  [C0603]  101.6 193.67 0 top
R120  33  [C0603]  101.6 191.77 0 top
R121  33  [C0603]  101.6 189.86 0 top
R122  33  [C0603]  142.24 198.12 180 top
R123  33  [C0603]  101.6 214.63 0 top
R124  33  [C0603]  101.6 212.72 0 top
R125  33  [C0603]  101.6 210.82 0 top
R126  33  [C0603]  101.6 208.91 0 top
R127  33  [C0603]  101.6 207.01 0 top
R128  33  [C0603]  101.6 205.1 0 top
R129  33  [C0603]  101.6 203.2 0 top
R130  33  [C0603]  101.6 201.29 0 top
R131  33  [C0603]  101.6 199.39 0 top
R132  33  [C0603]  101.6 197.48 0 top
R133  33  [C0603]  142.24 211.45 180 top
R134  49  [C0603]  147.95 209.55 180 top
R135  49  [C0603]  147.95 207.64 180 top
R136  49  [C0603]  147.95 205.74 0 top
R137  49  [C0603]  147.95 203.83 0 top
R138  49  [C0603]  147.95 201.93 180 top
R139  49  [C0603]  147.95 200.02 180 top
R144  10K  [C0603]  29.21 149.22 180 top
R145  1010  [C0603]  47.62 132.72 270 top
R146  10  [C0603]  59.69 132.72 90 top
R147  8K  [C0603]  57.15 132.72 90 top
R148  8K  [C0603]  62.23 132.72 90 top
R149  8K  [C0603]  29.21 153.03 0 top
R150  8K  [C0603]  29.21 154.94 0 top
R151  4K  [C0603]  29.21 151.13 0 top
R152  4K  [C0603]  24.77 158.75 0 top
R153  4K  [C0603]  29.21 156.84 0 top
R154  4K  [C0603]  66.67 173.35 90 top
R155  4K  [C0603]  75.56 157.48 0 top
R156  4K  [C0603]  75.56 161.29 0 top
R157  4K  [C0603]  75.56 149.86 0 top
R158  4K  [C0603]  75.56 155.57 0 top
R159  4K  [C0603]  79.38 153.67 0 top
R160  4K  [C0603]  79.38 155.57 0 top
R161  4K  [C0603]  75.56 159.38 0 top
R162  4K  [C0603]  75.56 153.67 0 top
R163  4K  [C0603]  59.05 168.27 90 top
R164  4K  [C0603]  79.38 151.76 0 top
R165  4K  [C0603]  79.38 149.86 0 top
R166  4K  [C0603]  54.61 132.72 270 top
R167  4K  [C0603]  75.56 151.76 0 top
R168  4K  [C0603]  64.77 173.35 90 top
R169  1K  [C0603]  34.29 142.88 180 top
R170  8K  [C0603]  40 150.49 0 top
R171  1K  [C0603]  48.89 168.27 270 top
R172  7510  [C0603]  29.21 158.75 0 top
R173  7510  [C0603]  43.18 168.27 270 top
R174  33  [C0603]  40 152.4 0 top
R175  4K  [C0603]  59.69 203.83 90 top
R176  4K  [C0603]  57.78 203.83 90 top
R177  10  [C0603]  41.91 229.87 270 top
R178  10  [C0603]  15.24 170.18 90 top
R179  10  [C0603]  11.43 170.18 90 top
R180  10  [C0603]  13.33 170.18 90 top
R181  10  [C0603]  9.52 170.18 90 top
R182  1K  [C0603]  55.88 203.83 90 top
R183  1K  [C0603]  40 229.87 270 top
R184  33  [C0603]  52.07 203.83 90 top
R185  4K  [C0603]  53.97 203.83 90 top
R186  5110  [C0603]  46.36 203.83 270 top
R187  5110  [C0603]  64.77 217.17 90 top
R188  5110  [C0603]  50.17 203.83 270 top
R189  75  [C0603]  29.21 164.46 180 top
R190  75  [C0603]  13.97 233.68 270 top
R191  75  [C0603]  19.68 233.68 270 top
R192  47K  [C0603]  38.73 180.97 270 top
R193  10K  [C0603]  44.45 194.94 270 top
R194  10K  [C0603]  53.34 195.58 270 top
R195  10K  [C0603]  87 166.37 270 top
R196  47K  [C0603]  45.72 182.88 90 top
R197  0  [C1206]  81.28 161.92 90 top
R198  10  [C0603]  43.18 189.23 270 top
R199  2K  [C0603]  57.78 188.59 90 top
R200  2K  [C0603]  49.53 182.88 270 top
R201  47K  [C0603]  59.69 188.59 270 top
R202  4K  [C0603]  43.81 182.88 270 top
R203  4K  [C0603]  55.88 188.59 90 top
R204  4K  [C0603]  80.01 166.37 90 top
R205  4K  [C0603]  85.09 166.37 90 top
R206  3K  [C0603]  53.34 182.88 270 top
R207  0  [C1206]  62.86 184.15 90 top
R208  10  [C0603]  49.53 178.44 270 top
R209  10  [C0603]  44.45 178.44 270 top
R210  10  [C0603]  49.53 137.16 90 top
R211  1K  [C0603]  45.72 137.16 90 top
R212  1K  [C0603]  51.44 137.16 270 top
R213  1K  [C0603]  70.48 146.69 0 top
R214  1K  [C0603]  75.56 146.69 0 top
R215  0  [C1206]  34.29 169.54 180 top
RN1  33  [NC06-4]  180.97 151.76 0 top
RN2  33  [NC06-4]  180.97 146.05 0 top
RN3  33  [NC06-4]  163.83 130.17 270 top
RN4  33  [NC06-4]  204.47 111.76 180 top
RN5  33  [NC06-4]  180.97 140.34 0 top
RN6  33  [NC06-4]  143.51 118.11 180 top
RN7  33  [NC06-4]  204.47 118.11 180 top
RN8  33  [NC06-4]  180.97 134.62 0 top
RN9  33  [NC06-4]  214.63 118.11 180 top
RN10  33  [NC06-4]  173.99 111.76 180 top
RN11  33  [NC06-4]  153.67 111.76 180 top
RN12  33  [NC06-4]  184.15 111.76 180 top
RN13  33  [NC06-4]  180.97 128.91 0 top
RN14  33  [NC06-4]  173.99 118.11 180 top
RN15  33  [NC06-4]  194.31 118.11 180 top
RN16  33  [NC06-4]  184.15 118.11 180 top
RN17  33  [NC06-4]  194.31 111.76 180 top
RN18  33  [NC06-4]  214.63 111.76 180 top
ST1  SW29/VI  [CON32A]  40.64 238.76 0 top
U2  ICS950201GT  [TSSOP56A]  124.46 203.2 0 top
U3  MCH  [BGA593A]  127.64 153.03 180 top
U4  27MHZ  [SQU04B]  34.29 147.95 90 top
U5  GRAPHIC  [BGA385A]  55.25 153.03 180 top
U6  74LVT125  [SO14]  19.05 216.53 180 top
U7  74LVT125  [SO14]  8.89 216.53 180 top
U8  SiI164CT64  [TQFP64D]  52.07 215.9 180 top
U9  PAC_VGA100  [SO16B]  32.38 215.9 180 top
U10  LP3965EMP-ADJ  [SOT223-5]  46.36 189.23 270 top
U11  LP3965EMP-ADJ  [SOT223-5]  52.07 189.23 270 top
U12  LP3965EMP-ADJ  [SOT223-5]  86.36 162.56 180 top
XT1  14MHZ3181/QA  [QUA02BSMD]  118.75 217.8 0 top

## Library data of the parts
C1 C62 C63 C103 C105 C107 C271 C273-C276 = CAP0603: User Part Number: ***; Tolerance: 10%; part number: CAP0603-0.01PF,10%,25V; tolerance: 10%; signal model: CAP0603_C0603_1pF
C61 C243 = CAP0603: User Part Number: ***; Tolerance: 10%; part number: CAP0603-0.1PF,10%,25V; tolerance: 10%; signal model: CAP0603_0_1PF_10__25V_0_1PF_C0A_0_1PF
C64-C66 C68 = CAP1206: User Part Number: ***; Tolerance: 10%; part number: CAP1206-0.1PF,10%,25V; tolerance: 10%; signal model: CAP1206_C1206_1pF
C67 C73 C74 C79 C82 C84-C96 C99-C102 C104 C106 C127 C207-C214 C224 C225 C229 C235 C236 C242 C244-C270 C272 C277-C293 = CAP0603: User Part Number: ***; Tolerance: 10%; part number: CAP0603-0.1PF,10%,25V; tolerance: 10%; signal model: CAP0603_C0603_1pF
C69 C72 = CAP1206_X5R: User Part Number: ***; Tolerance: 10%; part number: CAP1206_X5R-10UF,10%,25V; tolerance: 10%; signal model: CAP1206_X5R_C1206_1pF
C70 C71 = CAP_POL: User Part Number: ***; Tolerance: 10%; part number: CAP_POL-33UF,10%,12V; tolerance: 10%; signal model: CAP_POL_TAJC_1pF
C75 C77 = CAP_POL: User Part Number: ***; Tolerance: 10%; part number: CAP_POL-100UF,10%,12V; tolerance: 10%; signal model: CAP_POL_ELK01G_1pF
C76 C78 = CAP_POL: User Part Number: ***; Tolerance: 10%; part number: CAP_POL-100UF,10%,12V; tolerance: 10%; signal model: CAP_POL_TAJC_1pF
C80 C81 C83 C97 C98 = CAP1206_X7R: User Part Number: ***; Tolerance: 10%; part number: CAP1206_X7R-10UF,10%,10V; tolerance: 10%; signal model: CAP1206_X7R_C1206_1pF
C108-C110 C112-C117 C119-C126 = CAP0603: User Part Number: ***; Tolerance: 10%; part number: CAP0603-10PF,10%,25V; tolerance: 10%; signal model: CAP0603_C0603_1pF
C111 C118 = CAP0603: User Part Number: ***; Tolerance: 10%; part number: CAP0603-10F,10%,25V; tolerance: 10%; signal model: CAP0603_C0603_1pF
C215 C216 C233 C239-C241 = CAP_POL: User Part Number: ***; Tolerance: 10%; part number: CAP_POL-4UF,10%,12V; tolerance: 10%; signal model: CAP_POL_TAJA_1pF
C217 C219-C221 C226-C228 C234 C237 C238 = CAP_POL: User Part Number: ***; Tolerance: 10%; part number: CAP_POL-22UF,10%,12V; tolerance: 10%; signal model: CAP_POL_TAJA_1pF
C218 C230-C232 = CAP0603: User Part Number: ***; Tolerance: 10%; part number: CAP0603-100PF,10%,25V; tolerance: 10%; signal model: CAP0603_C0603_1pF
C222 = CAP0603: User Part Number: ***; Tolerance: 10%; part number: CAP0603-47PF,10%,25V; tolerance: 10%; signal model: CAP0603_C0603_1pF
C223 = CAP0603: User Part Number: ***; Tolerance: 10%; part number: CAP0603-220PF,10%,25V; tolerance: 10%; signal model: CAP0603_C0603_1pF
CF1-CF8 = NFM60R_222: User Part Number: ***; Tolerance: ***
CN2 = DDR-SOCKET-184P: User Part Number: ***; Tolerance: ***; signal model: DDR_SOCKET_184P_DIMM_DIMM
CN4 = CONNECTOR DBL-PWM: User Part Number: ***; signal model: CONNECTOR_DBL_PWM_CON07ASMD_SMA_SM07_FA
CN5 = CONNECTOR CPIS: User Part Number: ***; Tolerance: ***; signal model: CONNECTOR_CPIS_CON30FSMD_SW30_A_SW30_VJ
CN6 = CONNECTOR SVIDEO: User Part Number: ***; signal model: CONNECTOR_SVIDEO_CON07DF_SW04_A_SW04_RB
D1 = BAT54_SOT: User Part Number: ***; Tolerance: ***
F1 = SMD075: Tolerance: ***; User Part Number: ***; signal model: SMD075_SMD075_2_SMD075_2
FB1 FB2 = BLM21B601S: User Part Number: ***; Tolerance: ***
FB3-FB18 = BLM11A601S: User Part Number: ***; Tolerance: ***
JP1 = JP2X1: Tolerance: ***; User Part Number: ***; signal model: JP2X1_SM02_RA_WWS02_SM02_RA
L3 L4 = IND_AIR: User Part Number: ***; Tolerance: ***; signal model: IND_AIR_IND02GSMD_1nH
L5-L16 = PLW3216S102: User Part Number: ***; Tolerance: ***; signal model: PLW3216S102_IND04DSMD_1nH
Q1 = BC847B_SOT: User Part Number: ***; Tolerance: ***
Q2 = SI4425DY: User Part Number: ***; Tolerance: ***
Q3 Q4 = 2N7002_SOT: User Part Number: ***; Tolerance: ***
R56 R58 R59 R100-R104 R106-R108 R169 R171 R182 R183 R213 R214 = RES0603Q: User Part Number: ***; Tolerance: 5%; part number: RES0603Q-1K,5%,1/8W; tolerance: 5%; signal model: RES0603Q_C0603_1Ohm
R57 = RES0603Q: User Part Number: ***; Tolerance: 5%; part number: RES0603Q-1.5K,5%,1/8W; tolerance: 5%; signal model: RES0603Q_C0603_1Ohm
R60 = RES0603Q: User Part Number: ***; Tolerance: 5%; part number: RES0603Q-6K,5%,1/8W; tolerance: 5%; signal model: RES0603Q_C0603_1Ohm
R61 R64 R199 R200 = RES0603Q: User Part Number: ***; Tolerance: 5%; part number: RES0603Q-2K,5%,1/8W; tolerance: 5%; signal model: RES0603Q_C0603_1Ohm
R62 R65-R77 R87-R91 R177-R181 R198 R208 R209 = RES0603Q: User Part Number: ***; Tolerance: 5%; part number: RES0603Q-10,5%,1/8W; tolerance: 5%; signal model: RES0603Q_C0603_1Ohm
R63 R97 = RES0603Q: User Part Number: ***; Tolerance: 5%; part number: RES0603Q-40,5%,1/8W; tolerance: 5%; signal model: RES0603Q_C0603_1Ohm
R78-R86 R116-R133 R174 R184 = RES0603Q: User Part Number: ***; Tolerance: 5%; part number: RES0603Q-33,5%,1/8W; tolerance: 5%; signal model: RES0603Q_C0603_1Ohm
R92 = RES0603Q: User Part Number: ***; Tolerance: 5%; part number: RES0603Q-300,5%,1/8W; tolerance: 5%; signal model: RES0603Q_C0603_1Ohm
R93 = RES0603Q: User Part Number: ***; Tolerance: 5%; part number: RES0603Q-150,5%,1/8W; tolerance: 5%; signal model: RES0603Q_C0603_1Ohm
R94 R95 = RES0603Q: User Part Number: ***; Tolerance: 5%; part number: RES0603Q-24,5%,1/8W; tolerance: 5%; signal model: RES0603Q_C0603_1Ohm
R96 = RES0603Q: User Part Number: ***; Tolerance: 5%; part number: RES0603Q-30,5%,1/8W; tolerance: 5%; signal model: RES0603Q_C0603_1Ohm
R98 R134-R139 = RES0603Q: User Part Number: ***; Tolerance: 5%; part number: RES0603Q-49,5%,1/8W; tolerance: 5%; signal model: RES0603Q_C0603_1Ohm
R99 = RES0603Q: User Part Number: ***; Tolerance: 5%; part number: RES0603Q-100,5%,1/8W; tolerance: 5%; signal model: RES0603Q_C0603_1Ohm
R105 R144 R193-R195 = RES0603Q: User Part Number: ***; Tolerance: 5%; part number: RES0603Q-10K,5%,1/8W; tolerance: 5%; signal model: RES0603Q_C0603_1Ohm
R109 = RES0603Q: User Part Number: ***; Tolerance: 5%; part number: RES0603Q-475,5%,1/8W; tolerance: 5%; signal model: RES0603Q_C0603_1Ohm
R110-R115 = RES0603Q: User Part Number: ***; Tolerance: 5%; part number: RES0603Q-27,5%,1/8W; tolerance: 5%; signal model: RES0603Q_C0603_1Ohm
R145 = RES0603Q: User Part Number: ***; Tolerance: 5%; part number: RES0603Q-1010,5%,1/8W; tolerance: 5%; signal model: RES0603Q_C0603_1Ohm
R146 = RES0603Q: User Part Number: ***; Tolerance: 5%; part number: RES0603Q-10,5%,1/8W; tolerance: 5%; signal model: 0R_C0603_1Ohm
R147-R150 R170 = RES0603Q: User Part Number: ***; Tolerance: 5%; part number: RES0603Q-8K,5%,1/8W; tolerance: 5%; signal model: RES0603Q_C0603_1Ohm
R151-R168 R175 R176 R185 R202-R205 = RES0603Q: User Part Number: ***; Tolerance: 5%; part number: RES0603Q-4K,5%,1/8W; tolerance: 5%; signal model: RES0603Q_C0603_1Ohm
R172 R173 = RES0603Q: User Part Number: ***; Tolerance: 5%; part number: RES0603Q-7510,5%,1/8W; tolerance: 5%; signal model: RES0603Q_C0603_1Ohm
R186-R188 = RES0603Q: User Part Number: ***; Tolerance: 5%; part number: RES0603Q-5110,5%,1/8W; tolerance: 5%; signal model: RES0603Q_C0603_1Ohm
R189-R191 = RES0603Q: User Part Number: ***; Tolerance: 5%; part number: RES0603Q-75,5%,1/8W; tolerance: 5%; signal model: RES0603Q_C0603_1Ohm
R192 R196 R201 = RES0603Q: User Part Number: ***; Tolerance: 5%; part number: RES0603Q-47K,5%,1/8W; tolerance: 5%; signal model: RES0603Q_C0603_1Ohm
R197 R207 R215 = RES0603Q: User Part Number: ***; Tolerance: 5%; part number: RES0603Q-0,5%,1.8W; tolerance: 5%; signal model: 0R_1206_C1206_1Ohm
R206 = RES0603Q: User Part Number: ***; Tolerance: 5%; part number: RES0603Q-3K,5%,1/8W; tolerance: 5%; signal model: RES0603Q_C0603_1Ohm
R210 = RES0603Q: User Part Number: ***; Tolerance: 5%; part number: RES0603Q-10,5%,1/8W; tolerance: 5%; signal model: RES0603Q_10_5__1_8W_10_10
R211 R212 = RES0603Q: User Part Number: ***; Tolerance: 5%; part number: RES0603Q-1K,5%,1/8W; tolerance: 5%; signal model: RES0603Q_1K_5__1_8W_1K_1K
RN1-RN18 = NC06_33RSERX4_SMD: User Part Number: ***; Tolerance: ***; signal model: NC06_33RSERX4_SMD_33_NC06_4_33
ST1 = DVI_INTERFACE: signal model: DVI_INTERFACE_SW29_VI_SW29_VI
U2 = ICS950201AF: Tolerance: ***; User Part Number: ***; signal model: ICS950201AF_ICS950201GT_TSSOP5A_ICS950201GT
U3 = MCH: User Part Number: ***; Tolerance: ***; signal model: MCH_BGA593A_MCH_MCH
U4 = OSC24M_SMD: User Part Number: ***; Tolerance: ***
U5 = GRAPHIC: User Part Number: ***; Tolerance: ***; signal model: GRAPHIC_BGA385A_GRAPHIC_GRAPHIC
U6 U7 = 74125LVT_SO+: User Part Number: ***; Tolerance: ***
U8 = SII164: User Part Number: ***; Tolerance: ***; signal model: SII164_TQFP64D
U9 = PAC_VGA100: User Part Number: ***; Tolerance: ***; signal model: PAC_VGA100_PAC_VGA100_SO16B_PAC_VGA100
U10-U12 = LP3965EMPX-ADJ: User Part Number: ***; Tolerance: ***
XT1 = CRYSTAL_14M3181_HC49: Tolerance: ***; User Part Number: ***

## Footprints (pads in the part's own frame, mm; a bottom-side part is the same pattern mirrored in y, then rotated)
BGA385A
  round 0.508 smd: A1(-11,11) A2(-10,11) A3(-9,11) A4(-8,11) A5(-7,11) A6(-6,11) A7(-5,11) A8(-4,11) A9(-3,11) A10(-2,11) A11(-1,11) A12(0,11) A13(1,11) A14(2,11) A15(3,11) A16(4,11) A17(5,11) A18(6,11) A19(7,11) A20(8,11) A21(9,11) A22(10,11) A23(11,11) AA1(-11,-9) AA2(-10,-9) AA3(-9,-9) AA4(-8,-9) AA5(-7,-9) AA6(-6,-9) AA7(-5,-9) AA8(-4,-9) AA9(-3,-9) AA10(-2,-9) AA11(-1,-9) AA12(0,-9) AA13(1,-9) AA14(2,-9) AA15(3,-9) AA16(4,-9) AA17(5,-9) AA18(6,-9) AA19(7,-9) AA20(8,-9) AA21(9,-9) AA22(10,-9) AA23(11,-9) AB1(-11,-10) AB2(-10,-10) AB3(-9,-10) AB4(-8,-10) AB5(-7,-10) AB6(-6,-10) AB7(-5,-10) AB8(-4,-10) AB9(-3,-10) AB10(-2,-10) AB11(-1,-10) AB12(0,-10) AB13(1,-10) AB14(2,-10) AB15(3,-10) AB16(4,-10) AB17(5,-10) AB18(6,-10) AB19(7,-10) AB20(8,-10) AB21(9,-10) AB22(10,-10) AB23(11,-10) AC1(-11,-11) AC2(-10,-11) AC3(-9,-11) AC4(-8,-11) AC5(-7,-11) AC6(-6,-11) AC7(-5,-11) AC8(-4,-11) AC9(-3,-11) AC10(-2,-11) AC11(-1,-11) AC12(0,-11) AC13(1,-11) AC14(2,-11) AC15(3,-11) AC16(4,-11) AC17(5,-11) AC18(6,-11) AC19(7,-11) AC20(8,-11) AC21(9,-11) AC22(10,-11) AC23(11,-11) B1(-11,10) B2(-10,10) B3(-9,10) B4(-8,10) B5(-7,10) B6(-6,10) B7(-5,10) B8(-4,10) B9(-3,10) B10(-2,10) B11(-1,10) B12(0,10) B13(1,10) B14(2,10) B15(3,10) B16(4,10) B17(5,10) B18(6,10) B19(7,10) B20(8,10) B21(9,10) B22(10,10) B23(11,10) C1(-11,9) C2(-10,9) C3(-9,9) C4(-8,9) C5(-7,9) C6(-6,9) C7(-5,9) C8(-4,9) C9(-3,9) C10(-2,9) C11(-1,9) C12(0,9) C13(1,9) C14(2,9) C15(3,9) C16(4,9) C17(5,9) C18(6,9) C19(7,9) C20(8,9) C21(9,9) C22(10,9) C23(11,9) D1(-11,8) D2(-10,8) D3(-9,8) D4(-8,8) D5(-7,8) D6(-6,8) D7(-5,8) D8(-4,8) D9(-3,8) D10(-2,8) D11(-1,8) D12(0,8) D13(1,8) D14(2,8) D15(3,8) D16(4,8) D17(5,8) D18(6,8) D19(7,8) D20(8,8) D21(9,8) D22(10,8) D23(11,8) E1(-11,7) E2(-10,7) E3(-9,7) E4(-8,7) E5(-7,7) E6(-6,7) E7(-5,7) E8(-4,7) E9(-3,7) E10(-2,7) E11(-1,7) E12(0,7) E13(1,7) E14(2,7) E15(3,7) E16(4,7) E17(5,7) E18(6,7) E19(7,7) E20(8,7) E21(9,7) E22(10,7) E23(11,7) F1(-11,6) F2(-10,6) F3(-9,6) F4(-8,6) F5(-7,6) F19(7,6) F20(8,6) F21(9,6) F22(10,6) F23(11,6) G1(-11,5) G2(-10,5) G3(-9,5) G4(-8,5) G5(-7,5) G19(7,5) G20(8,5) G21(9,5) G22(10,5) G23(11,5) H1(-11,4) H2(-10,4) H3(-9,4) H4(-8,4) H5(-7,4) H19(7,4) H20(8,4) H21(9,4) H22(10,4) H23(11,4) J1(-11,3) J2(-10,3) J3(-9,3) J4(-8,3) J5(-7,3) J19(7,3) J20(8,3) J21(9,3) J22(10,3) J23(11,3) K1(-11,2) K2(-10,2) K3(-9,2) K4(-8,2) K5(-7,2) K10(-2,2) K11(-1,2) K12(0,2) K13(1,2) K14(2,2) K19(7,2) K20(8,2) K21(9,2) K22(10,2) K23(11,2) L1(-11,1) L2(-10,1) L3(-9,1) L4(-8,1) L5(-7,1) L10(-2,1) L11(-1,1) L12(0,1) L13(1,1) L14(2,1) L19(7,1) L20(8,1) L21(9,1) L22(10,1) L23(11,1) M1(-11,0) M2(-10,0) M3(-9,0) M4(-8,0) M5(-7,0) M10(-2,0) M11(-1,0) M12(0,0) M13(1,0) M14(2,0) M19(7,0) M20(8,0) M21(9,0) M22(10,0) M23(11,0) N1(-11,-1) N2(-10,-1) N3(-9,-1) N4(-8,-1) N5(-7,-1) N10(-2,-1) N11(-1,-1) N12(0,-1) N13(1,-1) N14(2,-1) N19(7,-1) N20(8,-1) N21(9,-1) N22(10,-1) N23(11,-1) P1(-11,-2) P2(-10,-2) P3(-9,-2) P4(-8,-2) P5(-7,-2) P10(-2,-2) P11(-1,-2) P12(0,-2) P13(1,-2) P14(2,-2) P19(7,-2) P20(8,-2) P21(9,-2) P22(10,-2) P23(11,-2) R1(-11,-3) R2(-10,-3) R3(-9,-3) R4(-8,-3) R5(-7,-3) R19(7,-3) R20(8,-3) R21(9,-3) R22(10,-3) R23(11,-3) T1(-11,-4) T2(-10,-4) T3(-9,-4) T4(-8,-4) T5(-7,-4) T19(7,-4) T20(8,-4) T21(9,-4) T22(10,-4) T23(11,-4) U1(-11,-5) U2(-10,-5) U3(-9,-5) U4(-8,-5) U5(-7,-5) U19(7,-5) U20(8,-5) U21(9,-5) U22(10,-5) U23(11,-5) V1(-11,-6) V2(-10,-6) V3(-9,-6) V4(-8,-6) V5(-7,-6) V19(7,-6) V20(8,-6) V21(9,-6) V22(10,-6) V23(11,-6) W1(-11,-7) W2(-10,-7) W3(-9,-7) W4(-8,-7) W5(-7,-7) W6(-6,-7) W7(-5,-7) W8(-4,-7) W9(-3,-7) W10(-2,-7) W11(-1,-7) W12(0,-7) W13(1,-7) W14(2,-7) W15(3,-7) W16(4,-7) W17(5,-7) W18(6,-7) W19(7,-7) W20(8,-7) W21(9,-7) W22(10,-7) W23(11,-7) Y1(-11,-8) Y2(-10,-8) Y3(-9,-8) Y4(-8,-8) Y5(-7,-8) Y6(-6,-8) Y7(-5,-8) Y8(-4,-8) Y9(-3,-8) Y10(-2,-8) Y11(-1,-8) Y12(0,-8) Y13(1,-8) Y14(2,-8) Y15(3,-8) Y16(4,-8) Y17(5,-8) Y18(6,-8) Y19(7,-8) Y20(8,-8) Y21(9,-8) Y22(10,-8) Y23(11,-8)
BGA593A
  round 0.508 smd: A3(-13,15) A5(-11,15) A7(-9,15) A9(-7,15) A11(-5,15) A13(-3,15) A15(-1,15) A17(1,15) A19(3,15) A21(5,15) A23(7,15) A25(9,15) A27(11,15) AA1(-15,-5) AA2(-14,-5) AA3(-13,-5) AA4(-12,-5) AA5(-11,-5) AA6(-10,-5) AA7(-9,-5) AA8(-8,-5) AA9(-7,-5) AA21(5,-5) AA22(6,-5) AA23(7,-5) AA24(8,-5) AA25(9,-5) AA26(10,-5) AA27(11,-5) AA28(12,-5) AA29(13,-5) AB3(-13,-6) AB4(-12,-6) AB5(-11,-6) AB6(-10,-6) AB7(-9,-6) AB8(-8,-6) AB9(-7,-6) AB10(-6,-6) AB11(-5,-6) AB12(-4,-6) AB13(-3,-6) AB14(-2,-6) AB15(-1,-6) AB16(0,-6) AB17(1,-6) AB18(2,-6) AB19(3,-6) AB20(4,-6) AB21(5,-6) AB22(6,-6) AB23(7,-6) AB24(8,-6) AB25(9,-6) AB26(10,-6) AB27(11,-6) AC1(-15,-7) AC2(-14,-7) AC3(-13,-7) AC4(-12,-7) AC5(-11,-7) AC6(-10,-7) AC7(-9,-7) AC8(-8,-7) AC9(-7,-7) AC10(-6,-7) AC11(-5,-7) AC12(-4,-7) AC13(-3,-7) AC14(-2,-7) AC15(-1,-7) AC16(0,-7) AC17(1,-7) AC18(2,-7) AC19(3,-7) AC20(4,-7) AC21(5,-7) AC22(6,-7) AC23(7,-7) AC24(8,-7) AC25(9,-7) AC26(10,-7) AC27(11,-7) AC28(12,-7) AC29(13,-7) AD3(-13,-8) AD4(-12,-8) AD5(-11,-8) AD6(-10,-8) AD7(-9,-8) AD8(-8,-8) AD9(-7,-8) AD10(-6,-8) AD11(-5,-8) AD12(-4,-8) AD13(-3,-8) AD14(-2,-8) AD15(-1,-8) AD16(0,-8) AD17(1,-8) AD18(2,-8) AD19(3,-8) AD20(4,-8) AD21(5,-8) AD22(6,-8) AD23(7,-8) AD24(8,-8) AD25(9,-8) AD26(10,-8) AD27(11,-8) AE1(-15,-9) AE2(-14,-9) AE3(-13,-9) AE4(-12,-9) AE5(-11,-9) AE6(-10,-9) AE7(-9,-9) AE8(-8,-9) AE9(-7,-9) AE10(-6,-9) AE11(-5,-9) AE12(-4,-9) AE13(-3,-9) AE14(-2,-9) AE15(-1,-9) AE16(0,-9) AE17(1,-9) AE18(2,-9) AE19(3,-9) AE20(4,-9) AE21(5,-9) AE22(6,-9) AE23(7,-9) AE24(8,-9) AE25(9,-9) AE26(10,-9) AE27(11,-9) AE28(12,-9) AE29(13,-9) AF3(-13,-10) AF4(-12,-10) AF5(-11,-10) AF6(-10,-10) AF7(-9,-10) AF8(-8,-10) AF9(-7,-10) AF10(-6,-10) AF11(-5,-10) AF12(-4,-10) AF13(-3,-10) AF14(-2,-10) AF15(-1,-10) AF16(0,-10) AF17(1,-10) AF18(2,-10) AF19(3,-10) AF20(4,-10) AF21(5,-10) AF22(6,-10) AF23(7,-10) AF24(8,-10) AF25(9,-10) AF26(10,-10) AF27(11,-10) AG1(-15,-11) AG2(-14,-11) AG3(-13,-11) AG4(-12,-11) AG5(-11,-11) AG6(-10,-11) AG7(-9,-11) AG8(-8,-11) AG9(-7,-11) AG10(-6,-11) AG11(-5,-11) AG12(-4,-11) AG13(-3,-11) AG14(-2,-11) AG15(-1,-11) AG16(0,-11) AG17(1,-11) AG18(2,-11) AG19(3,-11) AG20(4,-11) AG21(5,-11) AG22(6,-11) AG23(7,-11) AG24(8,-11) AG25(9,-11) AG26(10,-11) AG27(11,-11) AG28(12,-11) AG29(13,-11) AH2(-14,-12) AH3(-13,-12) AH5(-11,-12) AH7(-9,-12) AH9(-7,-12) AH11(-5,-12) AH13(-3,-12) AH15(-1,-12) AH17(1,-12) AH19(3,-12) AH21(5,-12) AH23(7,-12) AH25(9,-12) AH27(11,-12) AH28(12,-12) AJ3(-13,-13) AJ5(-11,-13) AJ7(-9,-13) AJ9(-7,-13) AJ11(-5,-13) AJ13(-3,-13) AJ15(-1,-13) AJ17(1,-13) AJ19(3,-13) AJ21(5,-13) AJ23(7,-13) AJ25(9,-13) AJ27(11,-13) B2(-14,14) B3(-13,14) B5(-11,14) B7(-9,14) B9(-7,14) B11(-5,14) B13(-3,14) B15(-1,14) B17(1,14) B19(3,14) B21(5,14) B23(7,14) B25(9,14) B27(11,14) B28(12,14) C1(-15,13) C2(-14,13) C3(-13,13) C4(-12,13) C5(-11,13) C6(-10,13) C7(-9,13) C8(-8,13) C9(-7,13) C10(-6,13) C11(-5,13) C12(-4,13) C13(-3,13) C14(-2,13) C15(-1,13) C16(0,13) C17(1,13) C18(2,13) C19(3,13) C20(4,13) C21(5,13) C22(6,13) C23(7,13) C24(8,13) C25(9,13) C26(10,13) C27(11,13) C28(12,13) C29(13,13) D3(-13,12) D4(-12,12) D5(-11,12) D6(-10,12) D7(-9,12) D8(-8,12) D9(-7,12) D10(-6,12) D11(-5,12) D12(-4,12) D13(-3,12) D14(-2,12) D15(-1,12) D16(0,12) D17(1,12) D18(2,12) D19(3,12) D20(4,12) D21(5,12) D22(6,12) D23(7,12) D24(8,12) D25(9,12) D26(10,12) D27(11,12) E1(-15,11) E2(-14,11) E3(-13,11) E4(-12,11) E5(-11,11) E6(-10,11) E7(-9,11) E8(-8,11) E9(-7,11) E10(-6,11) E11(-5,11) E12(-4,11) E13(-3,11) E14(-2,11) E15(-1,11) E16(0,11) E17(1,11) E18(2,11) E19(3,11) E20(4,11) E21(5,11) E22(6,11) E23(7,11) E24(8,11) E25(9,11) E26(10,11) E27(11,11) E28(12,11) E29(13,11) F3(-13,10) F4(-12,10) F5(-11,10) F6(-10,10) F7(-9,10) F8(-8,10) F9(-7,10) F10(-6,10) F11(-5,10) F12(-4,10) F13(-3,10) F14(-2,10) F15(-1,10) F16(0,10) F17(1,10) F18(2,10) F19(3,10) F20(4,10) F21(5,10) F22(6,10) F23(7,10) F24(8,10) F25(9,10) F26(10,10) F27(11,10) G1(-15,9) G2(-14,9) G3(-13,9) G4(-12,9) G5(-11,9) G6(-10,9) G7(-9,9) G8(-8,9) G9(-7,9) G10(-6,9) G11(-5,9) G12(-4,9) G13(-3,9) G14(-2,9) G15(-1,9) G16(0,9) G17(1,9) G18(2,9) G19(3,9) G20(4,9) G21(5,9) G22(6,9) G23(7,9) G24(8,9) G25(9,9) G26(10,9) G27(11,9) G28(12,9) G29(13,9) H3(-13,8) H4(-12,8) H5(-11,8) H6(-10,8) H7(-9,8) H8(-8,8) H9(-7,8) H10(-6,8) H11(-5,8) H12(-4,8) H13(-3,8) H14(-2,8) H15(-1,8) H16(0,8) H17(1,8) H18(2,8) H19(3,8) H20(4,8) H21(5,8) H22(6,8) H23(7,8) H24(8,8) H25(9,8) H26(10,8) H27(11,8) J1(-15,7) J2(-14,7) J3(-13,7) J4(-12,7) J5(-11,7) J6(-10,7) J7(-9,7) J8(-8,7) J9(-7,7) J21(5,7) J22(6,7) J23(7,7) J24(8,7) J25(9,7) J26(10,7) J27(11,7) J28(12,7) J29(13,7) K3(-13,6) K4(-12,6) K5(-11,6) K6(-10,6) K7(-9,6) K8(-8,6) K22(6,6) K23(7,6) K24(8,6) K25(9,6) K26(10,6) K27(11,6) L1(-15,5) L2(-14,5) L3(-13,5) L4(-12,5) L5(-11,5) L6(-10,5) L7(-9,5) L8(-8,5) L22(6,5) L23(7,5) L24(8,5) L25(9,5) L26(10,5) L27(11,5) L28(12,5) L29(13,5) M3(-13,4) M4(-12,4) M5(-11,4) M6(-10,4) M7(-9,4) M8(-8,4) M22(6,4) M23(7,4) M24(8,4) M25(9,4) M26(10,4) M27(11,4) N1(-15,3) N2(-14,3) N3(-13,3) N4(-12,3) N5(-11,3) N6(-10,3) N7(-9,3) N8(-8,3) N13(-3,3) N14(-2,3) N15(-1,3) N16(0,3) N17(1,3) N22(6,3) N23(7,3) N24(8,3) N25(9,3) N26(10,3) N27(11,3) N28(12,3) N29(13,3) P3(-13,2) P4(-12,2) P5(-11,2) P6(-10,2) P7(-9,2) P8(-8,2) P13(-3,2) P14(-2,2) P15(-1,2) P16(0,2) P17(1,2) P22(6,2) P23(7,2) P24(8,2) P25(9,2) P26(10,2) P27(11,2) R1(-15,1) R2(-14,1) R3(-13,1) R4(-12,1) R5(-11,1) R6(-10,1) R7(-9,1) R8(-8,1) R13(-3,1) R14(-2,1) R15(-1,1) R16(0,1) R17(1,1) R22(6,1) R23(7,1) R24(8,1) R25(9,1) R26(10,1) R27(11,1) R28(12,1) R29(13,1) T3(-13,0) T4(-12,0) T5(-11,0) T6(-10,0) T7(-9,0) T8(-8,0) T13(-3,0) T14(-2,0) T15(-1,0) T16(0,0) T17(1,0) T22(6,0) T23(7,0) T24(8,0) T25(9,0) T26(10,0) T27(11,0) U1(-15,-1) U2(-14,-1) U3(-13,-1) U4(-12,-1) U5(-11,-1) U6(-10,-1) U7(-9,-1) U8(-8,-1) U13(-3,-1) U14(-2,-1) U15(-1,-1) U16(0,-1) U17(1,-1) U22(6,-1) U23(7,-1) U24(8,-1) U25(9,-1) U26(10,-1) U27(11,-1) U28(12,-1) U29(13,-1) V3(-13,-2) V4(-12,-2) V5(-11,-2) V6(-10,-2) V7(-9,-2) V8(-8,-2) V22(6,-2) V23(7,-2) V24(8,-2) V25(9,-2) V26(10,-2) V27(11,-2) W1(-15,-3) W2(-14,-3) W3(-13,-3) W4(-12,-3) W5(-11,-3) W6(-10,-3) W7(-9,-3) W8(-8,-3) W22(6,-3) W23(7,-3) W24(8,-3) W25(9,-3) W26(10,-3) W27(11,-3) W28(12,-3) W29(13,-3) Y3(-13,-4) Y4(-12,-4) Y5(-11,-4) Y6(-10,-4) Y7(-9,-4) Y8(-8,-4) Y22(6,-4) Y23(7,-4) Y24(8,-4) Y25(9,-4) Y26(10,-4) Y27(11,-4)
C0603
  rect 0.508x0.813 smd: 1(-0.762,0) 2(0.762,0)
C0805
  rect 0.864x1.321 smd: 1(-1.016,0) 2(1.016,0)
C1206
  rect 1.016x1.575 smd: 1(-1.524,0) 2(1.524,0)
C1812
  rect 1.118x1.829 smd: 1(-1.968,0) 2(1.968,0)
CON07ASMD
  round 1.524 hole 0.914: 1(0,0) 2(0,2.54) 3(2.54,0) 4(2.54,2.54) 5(5.08,0) 6(5.08,2.54) 7(7.62,0)
CON07DF
  round 1.524 hole 0.914: 1(0,0) 2(0,2.54) 3(2.54,0) 4(2.54,2.54) 5(5.08,0) 6(5.08,2.54) 7(7.62,0)
CON30FSMD
  round 1.778 hole 1.981: (0,10.16)
  round 5.08 hole 2.743: (0,-13.335)
  rect 2.794x0.483 smd: 1(-1.905,8.255) 2(-1.905,6.985) 3(-1.905,5.715) 4(-1.905,4.445) 5(-1.905,3.175) 6(-1.905,1.905) 7(-1.905,0.635) 8(-1.905,-0.635) 9(-1.905,-1.905) 10(-1.905,-3.175) 11(-1.905,-4.445) 12(-1.905,-5.715) 13(-1.905,-6.985) 14(-1.905,-8.255) 15(-1.905,-9.525) 16(1.905,8.255) 17(1.905,6.985) 18(1.905,5.715) 19(1.905,4.445) 20(1.905,3.175) 21(1.905,1.905) 22(1.905,0.635) 23(1.905,-0.635) 24(1.905,-1.905) 25(1.905,-3.175) 26(1.905,-4.445) 27(1.905,-5.715) 28(1.905,-6.985) 29(1.905,-8.255) 30(1.905,-9.525)
CON32A
  round 1.143 hole 0.559: 1(0,0) 2(0,2.54) 3(2.54,0) 4(2.54,2.54) 5(5.08,0) 6(5.08,2.54) 7(7.62,0) 8(7.62,2.54) 9(10.16,0) 10(10.16,2.54) 11(12.7,0) 12(12.7,2.54) 13(15.24,0) 14(15.24,2.54) 15(17.78,0) 16(17.78,2.54) 17(20.32,0) 18(20.32,2.54) 19(22.86,0) 20(22.86,2.54) 21(25.4,0) 22(25.4,2.54) 23(27.94,0) 24(27.94,2.54) C1(30.48,0) C2(30.48,2.54) C3(33.02,0) C4(33.02,2.54) C5(35.56,0) C6(35.56,2.54) DR1(38.1,0) DR2(38.1,2.54)
DIMM184A
  round 4.064 hole 3.81: (1.905,3.81) (1.905,-50.8)
  round 1.143 hole 0.559: 1(0,0) 2(1.422,-0.94) 3(0,-1.93) 4(1.422,-2.896) 5(0,-3.861) 6(1.422,-4.826) 7(0,-5.791) 8(1.422,-6.756) 9(0,-7.722) 10(1.422,-8.687) 11(0,-9.652) 12(1.422,-10.617) 13(0,-11.582) 14(1.422,-12.548) 15(0,-13.513) 16(1.422,-14.478) 17(0,-15.443) 18(1.422,-16.408) 19(0,-17.374) 20(1.422,-18.339) 21(0,-19.304) 22(1.422,-20.269) 23(0,-21.234) 24(1.422,-22.2) 25(0,-23.165) 26(1.422,-24.13) 27(0,-25.095) 28(1.422,-26.06) 29(0,-27.026) 30(1.422,-27.991) 31(0,-28.956) 32(1.422,-29.921) 33(0,-30.886) 34(1.422,-31.852) 35(0,-32.817) 36(1.422,-33.782) 37(0,-34.747) 38(1.422,-35.712) 39(0,-36.678) 40(1.422,-37.643) 41(0,-38.608) 42(1.422,-39.573) 43(0,-40.538) 44(1.422,-41.504) 45(0,-42.469) 46(1.422,-43.434) 47(0,-44.399) 48(1.422,-45.364) 49(0,-46.33) 50(1.422,-47.295) 51(2.845,-46.33) 52(2.845,-44.399) 53(2.845,-42.469) 54(2.845,-40.538) 55(2.845,-38.608) 56(2.845,-36.678) 57(2.845,-34.747) 58(2.845,-32.817) 59(2.845,-30.886) 60(2.845,-28.956) 61(2.845,-27.026) 62(2.845,-25.095) 63(2.845,-23.165) 64(2.845,-21.234) 65(2.845,-19.304) 66(2.845,-17.374) 67(2.845,-15.443) 68(2.845,-13.513) 69(2.845,-11.582) 70(2.845,-9.652) 71(2.845,-7.722) 72(2.845,-5.791) 73(2.845,-3.861) 74(2.845,-1.93) 75(2.845,0) 76(4.267,-0.965) 77(4.267,-2.896) 78(4.267,-4.826) 79(4.267,-6.756) 80(4.267,-8.687) 81(4.267,-10.617) 82(4.267,-12.548) 83(4.267,-14.478) 84(4.267,-16.408) 85(4.267,-18.339) 86(4.267,-20.269) 87(4.267,-22.2) 88(4.267,-24.13) 89(4.267,-26.06) 90(4.267,-27.991) 91(4.267,-29.921) 92(4.267,-31.852) 93(4.267,-33.782) 94(4.267,-35.712) 95(4.267,-37.643) 96(4.267,-39.573) 97(4.267,-41.504) 98(4.267,-43.434) 99(4.267,-45.364) 100(4.267,-47.295) 101(5.69,-46.33) 102(5.69,-44.399) 103(5.69,-42.469) 104(5.69,-40.538) 105(5.69,-38.608) 106(5.69,-36.678) 107(5.69,-34.747) 108(5.69,-32.817) 109(5.69,-30.886) 110(5.69,-28.956) 111(5.69,-27.026) 112(5.69,-25.095) 113(5.69,-23.165) 114(5.69,-21.234) 115(5.69,-19.304) 116(5.69,-17.374) 117(5.69,-15.443) 118(5.69,-13.513) 119(5.69,-11.582) 120(5.69,-9.652) 121(5.69,-7.722) 122(5.69,-5.791) 123(5.69,-3.861) 124(5.69,-1.93) 125(5.69,0) 126(7.112,-0.965) 127(7.112,-2.896) 128(7.112,-4.826) 129(7.112,-6.756) 130(7.112,-8.687) 131(7.112,-10.617) 132(7.112,-12.548) 133(7.112,-14.478) 134(7.112,-16.408) 135(7.112,-18.339) 136(7.112,-20.269) 137(7.112,-22.2) 138(7.112,-24.13) 139(7.112,-26.06) 140(7.112,-27.991) 141(7.112,-29.921) 142(7.112,-31.852) 143(7.112,-33.782) 144(7.112,-35.712) 145(7.112,-37.643) 146(7.112,-39.573) 147(7.112,-41.504) 148(7.112,-43.434) 149(7.112,-45.364) 150(7.112,-47.295) 151(8.534,-46.33) 152(8.534,-44.399) 153(8.534,-42.469) 154(8.534,-40.538) 155(8.534,-38.608) 156(8.534,-36.678) 157(8.534,-34.747) 158(8.534,-32.817) 159(8.534,-30.886) 160(8.534,-28.956) 161(8.534,-27.026) 162(8.534,-25.095) 163(8.534,-23.165) 164(8.534,-21.234) 165(8.534,-19.304) 166(8.534,-17.374) 167(8.534,-15.443) 168(8.534,-13.513) 169(8.534,-11.582) 170(8.534,-9.652) 171(8.534,-7.722) 172(8.534,-5.791) 173(8.534,-3.861) 174(8.534,-1.93) 175(8.534,0) 176(9.957,-14.478) 177(9.957,-16.408) 178(9.957,-18.339) 179(9.957,-20.269) 180(9.957,-22.2) 181(9.957,-24.13) 182(9.957,-26.06) 183(9.957,-27.991) 184(9.957,-29.921)
ELK01G
  rect 2.032x2.032 smd: 1(-2.223,0) 2(2.223,0)
FM03ASMD
  rect 0.813x0.432 smd: 1(-0.889,0.94) 2(-0.889,-0.94) 3(0.889,0)
IND02GSMD
  custom 0.381x0.381 smd: 1(-2.477,0) 2(2.477,0)
IND04DSMD
  rect 1.27x0.635 smd: 1(-2.477,1.27) 2(-2.477,-1.27) 3(2.477,1.27) 4(2.477,-1.27)
